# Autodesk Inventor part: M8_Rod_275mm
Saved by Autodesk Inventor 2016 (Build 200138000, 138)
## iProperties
Created: 2015-11
Part Number: M8_Rod_275mm
Material: Generic
Document SubType Name: Modeling
Designer: John
Density: 1 g/cm^3
Appearance: Default
Author: John
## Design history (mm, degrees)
feature "Base1"
body "Solid1"
